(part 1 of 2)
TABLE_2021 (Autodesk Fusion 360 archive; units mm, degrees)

design "TABLE_2021" references "DistributeurCoin", "DistributeurBordure", "EchantillonRouge", "SupportCarreFouille", "BarreSeparation", "EchantillonVert", "CarreFouilleTresorJaune", "FriseJaune", "CarreFouille", "BaseTable", "CarreFouilleRadioactif", "Distributeur 2 Top", "Distributeur 2 Side", "CarreFouilleTresorViolet", "EchantillonBleu", "FriseViolet"
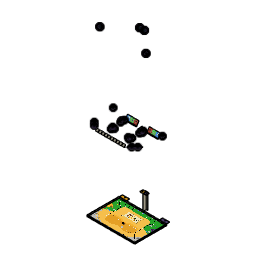
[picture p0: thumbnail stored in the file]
parameter "largeurCarreFouille" = 185 comment "largeur total du module de carre de fouille"
component_insert "Component Insert2" OffsetX 0 OffsetY 0 OffsetZ 0 AngleZ 0 OffsetX 0 OffsetY 0 OffsetZ 0 AngleZ 0 OffsetX 0 OffsetY 0 OffsetZ 0 AngleZ 0 OffsetX 0 OffsetY 0 OffsetZ 0 AngleZ 0 OffsetX 0 OffsetY 0 OffsetZ 0 AngleZ 0 OffsetX 0 OffsetY 0 OffsetZ 0 AngleZ 0 OffsetX 0 OffsetY 0 OffsetZ 0 AngleZ 0 OffsetX 0 OffsetY 0 OffsetZ 0 AngleZ 0 OffsetX 0 OffsetY 0 OffsetZ 0 AngleZ 0 OffsetX 0 OffsetY 0 OffsetZ 0 AngleZ 0 OffsetX 0 OffsetY 0 OffsetZ 0 AngleZ 0
joint "Assemble2" OffsetX 0 OffsetY 0 OffsetZ 0 AngleZ 0 alignAngle 180 alignOffsetX 0 alignOffsetY 0 alignOffsetZ 0
sketch "PlacementElements" plane through (0, 0, 0) normal (0, 0, 1) x axis (1, 0, 0)
  line L1 (3000, -2000) -> (0, -2000)
  line L2 (3000, 0) -> (3000, -2000)
  line L3 (0, 0) -> (3000, 0)
  line L4 (0, -2000) -> (0, 0)
  line L5 (1500, -2000) -> (1500, 0)
  line L6 (400, -400) -> (0, -400)
  line L7 (400, -1000) -> (400, -400)
  line L8 (0, -1000) -> (400, -1000)
  line L9 (0, -400) -> (0, -1000)
  line L10 (900, -555) -> (900, -795)
  line L11 (900, -675) -> (830, -675)
  line L12 (900, -720) -> (964.9519, -757.5)
  line L13 (835.0481, -757.5) -> (900, -720)
  line L14 (835.0481, -832.5) -> (835.0481, -757.5)
  line L15 (900, -870) -> (835.0481, -832.5)
  line L16 (964.9519, -832.5) -> (900, -870)
  line L17 (964.9519, -757.5) -> (964.9519, -832.5)
  line L18 (894.9519, -637.5) -> (894.9519, -712.5)
  line L19 (830, -600) -> (894.9519, -637.5)
  line L20 (765.0481, -637.5) -> (830, -600)
  line L21 (765.0481, -712.5) -> (765.0481, -637.5)
  line L22 (830, -750) -> (765.0481, -712.5)
  line L23 (894.9519, -712.5) -> (830, -750)
  line L24 (964.9519, -592.5) -> (900, -630)
  line L25 (964.9519, -517.5) -> (964.9519, -592.5)
  line L26 (900, -480) -> (964.9519, -517.5)
  line L27 (835.0481, -517.5) -> (900, -480)
  line L28 (835.0481, -592.5) -> (835.0481, -517.5)
  line L29 (900, -630) -> (835.0481, -592.5)
  line L30 (2100, -720) -> (2035.0481, -757.5)
  line L31 (2164.9519, -757.5) -> (2100, -720)
  line L32 (2164.9519, -832.5) -> (2164.9519, -757.5)
  line L33 (2100, -870) -> (2164.9519, -832.5)
  line L34 (2035.0481, -832.5) -> (2100, -870)
  line L35 (2035.0481, -757.5) -> (2035.0481, -832.5)
  line L36 (2170, -750) -> (2234.9519, -712.5)
  line L37 (2105.0481, -712.5) -> (2170, -750)
  line L38 (2105.0481, -637.5) -> (2105.0481, -712.5)
  line L39 (2170, -600) -> (2105.0481, -637.5)
  line L40 (2234.9519, -712.5) -> (2234.9519, -637.5)
  line L41 (2234.9519, -637.5) -> (2170, -600)
  line L42 (2035.0481, -592.5) -> (2100, -630)
  line L43 (2035.0481, -517.5) -> (2035.0481, -592.5)
  line L44 (2100, -480) -> (2035.0481, -517.5)
  line L45 (2164.9519, -517.5) -> (2100, -480)
  line L46 (2100, -630) -> (2164.9519, -592.5)
  line L47 (2164.9519, -592.5) -> (2164.9519, -517.5)
  line L48 (3000, -1000) -> (2600, -1000)
  line L49 (3000, -400) -> (3000, -1000)
  line L50 (2600, -1000) -> (2600, -400)
  line L51 (2600, -400) -> (3000, -400)
  line L52 (450, 22) -> (450, 222)
  line L53 (0, -2022) -> (1500, -2022)
  line L54 (800, -1550) -> (1150, -1550)
  line L55 (800, -1200) -> (800, -1550)
  line L56 (1150, -1200) -> (800, -1200)
  line L57 (1150, -1550) -> (1150, -1200)
  line L58 (800, -1200) -> (1150, -1550)
  line L59 (1150, -1200) -> (800, -1550)
  line L60 (975, -1200) -> (975, -1375)
  line L61 (800, -1375) -> (975, -1375)
  line L62 (2200, -1550) -> (1850, -1550)
  line L63 (1850, -1550) -> (1850, -1200)
  line L64 (1850, -1200) -> (2200, -1200)
  line L65 (2200, -1200) -> (2200, -1550)
  line L66 (-22, -2000) -> (-22, 0)
  line L67 (1450, -1300) -> (1550, -1300)
  line L68 (1450, -1200) -> (1450, -1300)
  line L69 (1550, -1200) -> (1450, -1200)
  line L70 (1550, -1300) -> (1550, -1200)
  line L71 (1450, -1200) -> (1550, -1300)
  line L72 (1550, -1200) -> (1450, -1300)
  point P6 (1500, 0)
  point P7 (1500, -2000)
  point P12 (1350, 0)
  point P13 (0, -1250)
  point P14 (0, -400)
  point P10 (900, -795)
  point P18 (900, -795)
  point P8 (900, -555)
  point P19 (900, -555)
  point P9 (830, -675)
  point P20 (830, -675)
  point P21 (900, -675)
  point P28 (900, -795)
  point P35 (830, -675)
  point P42 (900, -555)
  point P36 (900, -630)
  point P23 (900, -720)
  point P43 (3000, -1250)
  point P64 (3000, -400)
  point P15 (400, -400)
  point P65 (2600, -400)
  point P16 (400, -1000)
  point P62 (2600, -1000)
  point P17 (0, -1000)
  point P63 (3000, -1000)
  point P22 (964.9519, -757.5)
  point P44 (2035.0481, -757.5)
  point P45 (2100, -720)
  point P24 (835.0481, -757.5)
  point P46 (2164.9519, -757.5)
  point P25 (835.0481, -832.5)
  point P47 (2164.9519, -832.5)
  point P26 (900, -870)
  point P48 (2100, -870)
  point P27 (964.9519, -832.5)
  point P49 (2035.0481, -832.5)
  point P29 (894.9519, -712.5)
  point P52 (2105.0481, -712.5)
  point P30 (894.9519, -637.5)
  point P53 (2105.0481, -637.5)
  point P31 (830, -600)
  point P54 (2170, -600)
  point P32 (765.0481, -637.5)
  point P55 (2234.9519, -637.5)
  point P33 (765.0481, -712.5)
  point P50 (2234.9519, -712.5)
  point P34 (830, -750)
  point P51 (2170, -750)
  point P56 (2100, -630)
  point P37 (964.9519, -592.5)
  point P57 (2035.0481, -592.5)
  point P38 (964.9519, -517.5)
  point P58 (2035.0481, -517.5)
  point P39 (900, -480)
  point P59 (2100, -480)
  point P40 (835.0481, -517.5)
  point P60 (2164.9519, -517.5)
  point P41 (835.0481, -592.5)
  point P61 (2164.9519, -592.5)
  point P73 (2170, -675)
  point P74 (2100, -795)
  point P72 (2100, -555)
  point P75 (450, 0)
  point P77 (1650, 0)
  point P76 (2550, 0)
  point P80 (1500, -2022)
  point P81 (0, -2022)
  point P82 (1407.5, -2022)
  point P91 (1592.5, -2022)
  point P83 (1222.5, -2022)
  point P90 (1777.5, -2022)
  point P84 (1037.5, -2022)
  point P89 (1962.5, -2022)
  point P85 (852.5, -2022)
  point P88 (2147.5, -2022)
  point P86 (667.5, -2022)
  point P87 (2332.5, -2022)
  point P96 (975, -1375)
  point P11 (975, -1375)
  point P97 (975, -1375)
  point P98 (975, -1200)
  point P99 (975, -1375)
  point P100 (800, -1375)
  point P92 (1150, -1550)
  point P101 (1850, -1550)
  point P93 (800, -1550)
  point P102 (2200, -1550)
  point P94 (800, -1200)
  point P104 (2200, -1200)
  point P95 (1150, -1200)
  point P103 (1850, -1200)
  point P66 (892.3031, -1292.3031)
  point P107 (-22, -300)
  point P108 (-22, -337)
  point P109 (-22, -263)
  point P111 (3022, -300)
  point P112 (3022, -337)
  point P110 (3022, -263)
  point P117 (1500, -1250)
  point P1 (0, 0)
  point P113 (1550, -1300)
  point P116 (1550, -1200)
  point P114 (1450, -1300)
  midpoint L3 P6
  midpoint L1 P7
  coincident L3 P12
  coincident L4 P13
  horizontal L6
  vertical L7
  horizontal L8
  vertical L9
  coincident L4 P14
  coincident P10 P18
  coincident P8 P19
  vertical L10
  coincident P9 P20
  midpoint L10 P21
  horizontal L11
  coincident P10 P28
  coincident P9 P35
  coincident P8 P42
  coincident L10 P36
  vertical L18
  equal L19 L29
  equal L13 L23
  coincident L10 P23
  symmetric L5 P13 P43
  symmetric L5 P14 P64
  symmetric L5 P15 P65
  symmetric L5 P16 P62
  symmetric L5 P17 P63
  symmetric L5 P22 P44
  symmetric L5 P23 P45
  symmetric L5 P24 P46
  symmetric L5 P25 P47
  symmetric L5 P26 P48
  symmetric L5 P27 P49
  symmetric L5 P29 P52
  symmetric L5 P30 P53
  symmetric L5 P31 P54
  symmetric L5 P32 P55
  symmetric L5 P33 P50
  symmetric L5 P34 P51
  symmetric L5 P36 P56
  symmetric L5 P37 P57
  symmetric L5 P38 P58
  symmetric L5 P39 P59
  symmetric L5 P40 P60
  symmetric L5 P41 P61
  symmetric L5 P9 P73
  symmetric L5 P28 P74
  symmetric L5 P42 P72
  coincident L3 P75
  symmetric L5 P12 P77
  symmetric L5 P75 P76
  coincident P75 L52
  parallel L1 L53
  coincident L5 P80
  coincident L4 P81
  coincident L53 P82
  symmetric L5 P82 P91
  symmetric L5 P83 P90
  symmetric L5 P84 P89
  symmetric L5 P85 P88
  symmetric L5 P86 P87
  horizontal L54
  perpendicular L54 L55
  parallel L54 L56
  parallel L55 L57
  coincident L58 P96
  coincident L59 P96
  coincident P11 P97
  midpoint L56 P98
  coincident P11 P99
  midpoint L55 P100
  symmetric L5 P92 P101
  symmetric L5 P93 P102
  symmetric L5 P94 P104
  symmetric L5 P95 P103
  coincident P66 L58
  perpendicular L3 L66
  coincident L66 P107
  coincident L66 P108
  coincident L66 P109
  symmetric L5 P107 P111
  symmetric L5 P108 P112
  symmetric L5 P109 P110
  horizontal L67
  perpendicular L67 L68
  parallel L67 L69
  parallel L68 L70
  coincident L71 P117
  coincident L72 P117
  coincident L5 P117
  dimension "d26" distance L1 P11 = 625
  dimension "d27" distance L4 P11 = 975
  dimension "d28" distance L4 P10 = 900
  dimension "d29" distance P31 P34 = 150
  dimension "d31" distance L3 P35 = 675
  dimension "d32" distance P35 P42 = 120
  dimension "d33" distance P1 P13 = 1250
  dimension "d34" distance P14 P15 = 400
  dimension "d35" distance P15 P16 = 600
  dimension "d36" distance L3 L6 = 400
  dimension "d37" distance L10 P35 = 70
  dimension "d206" distance L5 P12 = 150
  dimension "d297" distance L1 P81 = 22
  dimension "d298" distance L5 P82 = 92.5 (= "largeurCarreFouille / 2")
  dimension "d425" distance L55 L57 = 350
  dimension "d426" distance L54 L56 = 350
  dimension "d427" distance P99 P100 = 175 (= "d426 / 2")
  dimension "d428" distance P97 P98 = 175 (= "d425 / 2")
  dimension "d549" distance L9 L66 = 22
  dimension "d550" distance P107 P109 = 37 (= "22 mm + 15 mm")
  dimension "d551" distance P107 P108 = 37 (= "d550")
  dimension "d552" distance P1 P107 = 300
  dimension "d605" distance P113 P116 = 100
  dimension "d606" distance P113 P114 = 100
  dimension "d607" distance L3 P117 = 1250
  dimension "d301" R-Pattern1-uDistance = 185 (= "largeurCarreFouille")
  dimension "d302" R-Pattern1-vDistance = 0
component_insert "Component Insert2"
component_insert "Insertion d'un composant22"
component_insert "Insertion d'un composant23"
component_insert "Component Insert4"
component_insert "Component Insert8"
component_insert "Insertion d'un composant24"
component_insert "Insertion d'un composant25"
component_insert "Component Insert11"
component_insert "Insertion d'un composant20"
component_insert "Insertion d'un composant21"
joint "Assemble3" OffsetX 0 OffsetY 0 OffsetZ 0 AngleZ 0 alignAngle 60 alignOffsetX 0 alignOffsetY 0 alignOffsetZ 0
joint "Assemble6" OffsetX 0 OffsetY 0 OffsetZ 0 AngleZ 0 alignAngle 15 alignOffsetX 0 alignOffsetY 0 alignOffsetZ 0
component_insert "Insertion d'un composant18"
component_insert "Insertion d'un composant19"
joint "Assemble9" OffsetX 0 OffsetY 0 OffsetZ 0 AngleZ 0 alignAngle -70 alignOffsetX 0 alignOffsetY 0 alignOffsetZ 0
joint "Assemble13" OffsetX 0 OffsetY 0 OffsetZ 0 AngleZ 0 alignAngle 60 alignOffsetX 0 alignOffsetY 0 alignOffsetZ 0 OffsetX 0 OffsetY 0 OffsetZ 0 AngleZ 0
component_insert "Insertion d'un composant3"
component_insert "Insertion d'un composant4"
joint "Assembler34" alignAngle -90 alignOffsetX 0 alignOffsetY 0 alignOffsetZ 0
joint "Assembler35" alignAngle -90 alignOffsetX 0 alignOffsetY 0 alignOffsetZ 0
component_insert "Component Insert3"
joint "Assemble19" OffsetX 0 OffsetY 0 OffsetZ 0 AngleZ 0 alignAngle -90 alignOffsetX 0 alignOffsetY 0 alignOffsetZ 0
component_insert "Component Insert5"
component_insert "Insertion d'un composant6"
component_insert "Insertion d'un composant7"
joint "Assemble20" OffsetX 0 OffsetY 0 OffsetZ 0 AngleZ 0 alignAngle 90 alignOffsetX 0 alignOffsetY 0 alignOffsetZ 0
joint "Assembler32" alignAngle 180 alignOffsetX 0 alignOffsetY 0 alignOffsetZ 0
joint "Assembler33" alignAngle 180 alignOffsetX 0 alignOffsetY 0 alignOffsetZ 0
component_insert "Component Insert3"
joint "Assemble21" OffsetX 0 OffsetY 0 OffsetZ 0 AngleZ 0 alignAngle 180 alignOffsetX 0 alignOffsetY 0 alignOffsetZ 0
component_insert "Insertion d'un composant11"
joint "Assembler36" alignAngle 180 alignOffsetX 0 alignOffsetY 0 alignOffsetZ 0
component_insert "Insertion d'un composant12"
joint "Assembler37" alignAngle 180 alignOffsetX 0 alignOffsetY 0 alignOffsetZ 0
component_insert "Insertion d'un composant13"
joint "Assembler38" alignAngle 180 alignOffsetX 0 alignOffsetY 0 alignOffsetZ 0
component_insert "Insertion d'un composant14"
joint "Assembler39" alignAngle 180 alignOffsetX 0 alignOffsetY 0 alignOffsetZ 0
component_insert "Insertion d'un composant15"
joint "Assembler40" alignAngle 180 alignOffsetX 0 alignOffsetY 0 alignOffsetZ 0
component_insert "Insertion d'un composant16"
joint "Assembler41" alignAngle 180 alignOffsetX 0 alignOffsetY 0 alignOffsetZ 0
component_insert "Insertion d'un composant17"
joint "Assembler42" alignAngle 180 alignOffsetX 0 alignOffsetY 0 alignOffsetZ 0
component_insert "Insertion d'un composant18"
joint "Assembler43" alignAngle 180 alignOffsetX 0 alignOffsetY 0 alignOffsetZ 0
component_insert "Insertion d'un composant19"
joint "Assembler44" alignAngle 180 alignOffsetX 0 alignOffsetY 0 alignOffsetZ 0
component_insert "Insertion d'un composant20"
joint "Assembler45" alignAngle 180 alignOffsetX 0 alignOffsetY 0 alignOffsetZ 0
component_insert "Insertion d'un composant8"
joint "Assembler46" alignAngle 90 alignOffsetX 0 alignOffsetY 0 alignOffsetZ 0
joint "Assembler47" alignAngle 0 alignOffsetX 0 alignOffsetY 0 alignOffsetZ 0
component_insert "Insertion d'un composant9"
joint "Assembler48" alignAngle 90 alignOffsetX 0 alignOffsetY 0 alignOffsetZ 0
joint "Assembler49" alignAngle 0 alignOffsetX 0 alignOffsetY 0 alignOffsetZ 0
component_insert "Insertion d'un composant14"
component_insert "Insertion d'un composant15"
component_insert "Insertion d'un composant16"
component_insert "Insertion d'un composant17"
component_insert "Component Insert1"
component_insert "Component Insert2"
component_insert "Component Insert3"
component_insert "Component Insert4"
component_insert "Component Insert5"
component_insert "Component Insert6"
component_insert "Component Insert7"
component_insert "Component Insert8"
component_insert "Component Insert9"
component_insert "Component Insert10"
joint "Assemble22" OffsetX 0 OffsetY 0 OffsetZ 0 AngleZ 0 alignAngle 180 alignOffsetX 0 alignOffsetY 0 alignOffsetZ 0
joint "Assemble23" OffsetX 0 OffsetY 0 OffsetZ 0 AngleZ 0 alignAngle 180 alignOffsetX 0 alignOffsetY 0 alignOffsetZ 0
joint "Assemble24" OffsetX 0 OffsetY 0 OffsetZ 0 AngleZ 0 alignAngle 180 alignOffsetX 0 alignOffsetY 0 alignOffsetZ 0
joint "Assemble25" OffsetX 0 OffsetY 0 OffsetZ 0 AngleZ 0 alignAngle 180 alignOffsetX 0 alignOffsetY 0 alignOffsetZ 0
joint "Assemble26" OffsetX 0 OffsetY 0 OffsetZ 0 AngleZ 0 alignAngle 180 alignOffsetX 0 alignOffsetY 0 alignOffsetZ 0
joint "Assemble27" OffsetX 0 OffsetY 0 OffsetZ 0 AngleZ 0 alignAngle 180 alignOffsetX 0 alignOffsetY 0 alignOffsetZ 0
joint "Assemble28" OffsetX 0 OffsetY 0 OffsetZ 0 AngleZ 0 alignAngle 180 alignOffsetX 0 alignOffsetY 0 alignOffsetZ 0
joint "Assemble29" OffsetX 0 OffsetY 0 OffsetZ 0 AngleZ 0 alignAngle 180 alignOffsetX 0 alignOffsetY 0 alignOffsetZ 0
joint "Assemble30" OffsetX 0 OffsetY 0 OffsetZ 0 AngleZ 0 alignAngle 180 alignOffsetX 0 alignOffsetY 0 alignOffsetZ 0
joint "Assemble31" OffsetX 0 OffsetY 0 OffsetZ 0 AngleZ 0 alignAngle 180 alignOffsetX 0 alignOffsetY 0 alignOffsetZ 0
joint "Assembler54" alignAngle -15 alignOffsetX 0 alignOffsetY 0 alignOffsetZ 0
joint "Assembler55" alignAngle 15 alignOffsetX 0 alignOffsetY 0 alignOffsetZ 0
joint "Assembler56" alignAngle 75 alignOffsetX 0 alignOffsetY 0 alignOffsetZ 0
joint "Assembler57" alignAngle 25 alignOffsetX 0 alignOffsetY 0 alignOffsetZ 0
joint "Assembler58" alignAngle 60 alignOffsetX 0 alignOffsetY 0 alignOffsetZ 0
joint "Assembler59" alignAngle 60 alignOffsetX 0 alignOffsetY 0 alignOffsetZ 0
joint "Assembler60" alignAngle 60 alignOffsetX 0 alignOffsetY 0 alignOffsetZ 0
joint "Assembler61" alignAngle 60 alignOffsetX 0 alignOffsetY 0 alignOffsetZ 0
component_insert "Insertion d'un composant10"
joint "Assembler62" alignAngle -90 alignOffsetX 0 alignOffsetY 0 alignOffsetZ 48 (= "70.00 mm - 22 mm")
component_insert "Insertion d'un composant11"
joint "Assembler63" alignAngle 180 alignOffsetX 0 alignOffsetY 0 alignOffsetZ 0
component_insert "Insertion d'un composant26"
component_insert "Insertion d'un composant27"
joint "Assembler67" alignAngle 90 alignOffsetX 0 alignOffsetY 0 alignOffsetZ 48
component_insert "Insertion d'un composant5"
joint "Assembler68" alignAngle -270 alignOffsetX 0 alignOffsetY -55 alignOffsetZ 0
joint "Assembler69" alignAngle -75 alignOffsetX 0 alignOffsetY 0 alignOffsetZ 0
joint "Assembler70" alignAngle 105 alignOffsetX 0 alignOffsetY 0 alignOffsetZ 0
joint "Assembler71" alignAngle -75 alignOffsetX 0 alignOffsetY 0 alignOffsetZ 0
joint "Assembler72" alignAngle 105 alignOffsetX 0 alignOffsetY 0 alignOffsetZ 0
joint "Assembler73" alignAngle 180 alignOffsetX 0 alignOffsetY 22 alignOffsetZ 0
joint "Assembler74" alignAngle 180 alignOffsetX 0 alignOffsetY 22 alignOffsetZ 0
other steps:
joint_origin "JointOrigin2" OffsetX 0 OffsetY 0 OffsetZ 0 AngleZ 0
create_component "CreateComponent1"
create_component "CreateComponent2"
create_component "CreateComponent3"
joint_origin "JointOrigin22" OffsetX 0 OffsetY 0 OffsetZ 0 AngleZ 0
joint_origin "JointOrigin23" OffsetX 0 OffsetY 0 OffsetZ 0 AngleZ 0
joint_origin "JointOrigin24" sketch "PlacementElements" OffsetX 0 OffsetY 0 OffsetZ 0 AngleZ 0
create_component "CreateComponent4"
joint_origin "JointOrigin25" OffsetX 0 OffsetY 0 OffsetZ 0 AngleZ 0
joint_origin "JointOrigin26" OffsetX 0 OffsetY 0 OffsetZ 0 AngleZ 0
joint_origin "JointOrigin27" OffsetX 0 OffsetY 0 OffsetZ 0 AngleZ 0
joint_origin "JointOrigin28" OffsetX 0 OffsetY 0 OffsetZ 0 AngleZ 0
joint_origin "JointOrigin29" OffsetX 0 OffsetY 0 OffsetZ 0 AngleZ 0
joint_origin "JointOrigin30" OffsetX 0 OffsetY 0 OffsetZ 0 AngleZ 0
joint_origin "JointOrigin31" OffsetX 0 OffsetY 0 OffsetZ 0 AngleZ 0
joint_origin "JointOrigin32" OffsetX 0 OffsetY 0 OffsetZ 0 AngleZ 0
joint_origin "JointOrigin33" OffsetX 0 OffsetY 0 OffsetZ 0 AngleZ 0
joint_origin "JointOrigin34" OffsetX 0 OffsetY 0 OffsetZ 0 AngleZ 0
joint_origin "JointOrigin35"
joint_origin "JointOrigin36"
joint_origin "JointOrigin51"
joint_origin "JointOrigin52"
joint_origin "JointOrigin53"
joint_origin "JointOrigin56"
joint_origin "JointOrigin57"
joint_origin "JointOrigin62"
joint_origin "JointOrigin63"
joint_origin "JointOrigin64"
joint_origin "JointOrigin65"
joint_origin "JointOrigin66"
joint_origin "JointOrigin67"
joint_origin "JointOrigin69"
joint_origin "JointOrigin79"
joint_origin "JointOrigin81"
joint_origin "JointOrigin82"
joint_origin "JointOrigin83"
joint_origin "JointOrigin84"
joint_origin "JointOrigin85"
joint_origin "JointOrigin86"
joint_origin "JointOrigin87"
joint_origin "JointOrigin88"
joint_origin "JointOrigin90"
joint_origin "JointOrigin91"
joint_origin "JointOrigin92"
joint_origin "JointOrigin93"
joint_origin "JointOrigin94"
joint_origin "JointOrigin95"

design "DistributeurBordure" references "EchantillonBleu"
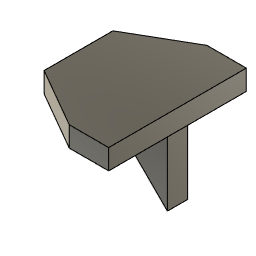
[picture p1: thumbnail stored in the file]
parameter "d10" = 70
sketch "Esquisse1" plane through (0, 0, 0) normal (0, 0, 1) x axis (1, 0, 0)
  line L1 (0, -100) -> (0, 100)
  line L2 (-22, -100) -> (0, -100)
  line L3 (-22, 100) -> (-22, -100)
  line L4 (0, 100) -> (-22, 100)
  point P1 (0, 0)
  vertical L1
  perpendicular L1 L2
  perpendicular L2 L3
  perpendicular L1 L4
  dimension "d1" distance L1 L3 = 22
  dimension "d2" distance P1 L4 = 100
  dimension "d3" distance L2 L4 = 200 (= "d2 * 2")
extrude "Extrusion1" new body sketch "Esquisse1" along normal blind 92 (= "70 mm + 22 mm")
sketch "Esquisse1" plane through (0, 0, 92) normal (0, 0, 1) x axis (-1, 0, 0)
  line L1 (22, 100) -> (22, -100)
  line L2 (0, 100) -> (22, 100)
  line L3 (0, -100) -> (0, 100)
  line L4 (22, -100) -> (0, -100)
  line L5 (0, -37) -> (64.287, -37)
  line L6 (0, -15) -> (0, -37)
  line L7 (64.287, -15) -> (0, -15)
  line L8 (64.287, -37) -> (64.287, -15)
  line L9 (64.287, 15) -> (0, 15)
  line L10 (64.287, 37) -> (64.287, 15)
  line L11 (0, 37) -> (64.287, 37)
  line L12 (0, 15) -> (0, 37)
  point P8 (0, -15)
  point P10 (0, 15)
  point P1 (0, 0)
  point P11 (64.287, 15)
  point P12 (64.287, 37)
  point P6 (64.287, -37)
  point P9 (64.287, -15)
  horizontal L5
  vertical L6
  horizontal L7
  vertical L8
  coincident L3 P8
  horizontal L9
  vertical L10
  horizontal L11
  vertical L12
  coincident L3 P10
  dimension "d6" distance P1 P8 = 15
  dimension "d7" distance P1 P10 = 15 (= "d6")
  dimension "d8" distance P11 P12 = 22
  dimension "d9" distance P6 P9 = 22 (= "d8")
  dimension "d42" distance L1 L8 = 42.287
  dimension "d43" distance L1 L10 = 42.287 (= "d42")
extrude "Extrusion1" new body sketch "Esquisse1" profile of L1 L5 L7 L8 L9 L10 L11 against normal blind 92
extrude "Extrusion2" add sketch "Esquisse1" profile of L1 L3 L5 L6 L7 L8 L9 L10 L11 L12 along normal blind 120
sketch "Esquisse2" plane through (0, -37, 0) normal (0, -1, 0) x axis (1, 0, 0)
  line L1 (-64.287, 0) -> (-64.287, 212)
  line L2 (-22, 0) -> (-64.287, 0)
  line L3 (-22, 92) -> (-22, 0)
  line L4 (0, 92) -> (-22, 92)
  line L5 (0, 212) -> (0, 92)
  line L6 (-64.287, 212) -> (0, 212)
  line L7 (-64.287, 175.3484) -> (-4.8706, 72.4361)
  line L8 (0, 108) -> (-19.0526, 97)
  line L9 (-11, 127.0526) -> (0, 108)
  line L10 (-30.0526, 116.0526) -> (-11, 127.0526)
  line L11 (-27.7128, 92) -> (-64.287, 155.3484)
  line L12 (-19.0526, 97) -> (-27.7128, 92)
  line L13 (-64.287, 92) -> (-22, 92)
  line L14 (-22, 82.1051) -> (-27.7128, 92)
  point P9 (-64.287, 175.3484)
  point P10 (-19.0526, 97)
  point P13 (-30.0526, 116.0526)
  point P14 (-64.287, 155.3484)
  point P16 (-19.0526, 97)
  point P11 (0, 108)
  point P5 (-22, 92)
  point P17 (-22, 92)
  point P18 (-64.287, 92)
  point P15 (-27.7128, 92)
  point P19 (-22, 82.1051)
  point P12 (-11, 127.0526)
  coincident L1 P9
  coincident L7 P10
  perpendicular L7 L8
  perpendicular L8 L9
  coincident L7 P13
  perpendicular L7 L10
  coincident L1 P14
  parallel L7 L11
  coincident L7 P16
  perpendicular L7 L12
  collinear L8 L12
  coincident L5 P11
  coincident P5 P17
  coincident L1 P18
  perpendicular L1 L13
  coincident P15 L13
  coincident L3 P19
  perpendicular L12 L14
  dimension "d16" distance P11 P12 = 22
  dimension "d17" distance P10 P11 = 22
  dimension "d18" angle L5 L7 = 30
  dimension "d19" distance L7 L11 = 10
extrude "Extrusion3" cut sketch "Esquisse2" profile of L1 L4 L5 L6 L7 L8 L9 L10 L11 L12 L13 against normal blind 74
sketch "Esquisse1" plane through (19.0526, 0, 11) normal (0.866, 0, 0.5) x axis (0, 1, 0)
  line L1 (-15, 166.6791) -> (-15, 93.5307)
  line L2 (-37, 93.5307) -> (-37, 166.6791)
  line L3 (-15, 93.5307) -> (-37, 93.5307)
  line L4 (15, 93.5307) -> (15, 166.6791)
  line L5 (37, 93.5307) -> (15, 93.5307)
  line L6 (37, 166.6791) -> (37, 93.5307)
  line L7 (37.5, 93.5307) -> (-37.5, 93.5307)
  line L8 (37.5, 223.5307) -> (37.5, 93.5307)
  line L9 (-37.5, 223.5307) -> (37.5, 223.5307)
  line L10 (-37.5, 93.5307) -> (-37.5, 223.5307)
  line L11 (37.5, 166.6791) -> (37, 166.6791)
  line L12 (-37.5, 166.6791) -> (-37, 166.6791)
  line L13 (-37, 166.6791) -> (-15, 166.6791)
  line L14 (15, 166.6791) -> (37, 166.6791)
  point P9 (37, 166.6791)
  point P14 (37, 166.6791)
  point P15 (37.5, 166.6791)
  point P4 (-37, 166.6791)
  point P16 (-37, 166.6791)
  point P17 (-37.5, 166.6791)
  point P12 (37.5, 223.5307)
  point P13 (-37.5, 223.5307)
  perpendicular L2 L7
  perpendicular L3 L8
  perpendicular L8 L9
  perpendicular L9 L10
  collinear L5 L7
  coincident P9 P14
  coincident L8 P15
  perpendicular L8 L11
  coincident P4 P16
  coincident L10 P17
  perpendicular L10 L12
  equal L11 L12
  dimension "d22" distance P12 P13 = 75
  dimension "d23" distance L7 L9 = 130
extrude "Extrusion1" new body sketch "Esquisse1" profile of L1 L2 L3 L4 L5 L6 L7 L8 L9 L10 along normal blind 10
sketch "Esquisse1" plane through (0, -37.5, 0) normal (0, -1, 0) x axis (1, 0, 0)
  line L1 (-27.7128, 92) -> (-92.7128, 204.5833)
  line L2 (-19.0526, 97) -> (-27.7128, 92)
  line L3 (-84.0526, 209.5833) -> (-19.0526, 97)
  line L4 (-92.7128, 204.5833) -> (-84.0526, 209.5833)
  line L5 (0, 108) -> (-19.0526, 97)
  line L6 (-11, 127.0526) -> (0, 108)
  line L7 (-30.0526, 116.0526) -> (-11, 127.0526)
  line L8 (-30.0526, 116.0526) -> (-19.0526, 97)
  point P4 (-19.0526, 97)
  point P6 (-19.0526, 97)
  point P9 (-30.0526, 116.0526)
  point P10 (-19.0526, 97)
  point P7 (0, 108)
  point P8 (-11, 127.0526)
  coincident P4 P6
  perpendicular L3 L5
  perpendicular L5 L6
  coincident L3 P9
  perpendicular L3 L7
  coincident P4 P10
  dimension "d26" distance P7 P8 = 22
  dimension "d27" distance P8 P9 = 22
extrude "Extrusion1" new body sketch "Esquisse1" profile of L3 L5 L6 L7 L8 against normal blind 75
joint "Assembler1" alignAngle 180 alignOffsetX 0 alignOffsetY 0 alignOffsetZ 0
joint "Assembler2" alignAngle -90 alignOffsetX 0 alignOffsetY 0 alignOffsetZ 15
joint "Assembler3" alignAngle 0 alignOffsetX 0 alignOffsetY 0 alignOffsetZ 0
sketch "Esquisse1" plane through (0, -37, 0) normal (0, -1, 0) x axis (1, 0, 0)
  line L1 (-64.287, 155.3484) -> (-27.7128, 92)
  line L2 (-64.287, 0) -> (-64.287, 155.3484)
  line L3 (-22, 0) -> (-64.287, 0)
  line L4 (-22, 92) -> (-22, 0)
  line L5 (-27.7128, 92) -> (-22, 92)
  line L6 (-22, 82.1051) -> (-27.7128, 92)
  point P2 (-27.7128, 92)
  point P7 (-27.7128, 92)
  coincident P2 P7
  parallel L1 L6
extrude "Extrusion4" cut sketch "Esquisse1" profile of L4 L5 L6 against normal blind 74
sketch "Esquisse1" plane through (0, 0, 92) normal (0, 0, 1) x axis (-1, 0, 0)
  line L1 (22, 100) -> (22, -100)
  line L2 (0, 100) -> (22, 100)
  line L3 (0, -100) -> (0, 100)
  line L4 (22, -100) -> (0, -100)
  line L5 (132, -75) -> (22, -75)
  line L6 (132, 75) -> (132, -75)
  line L7 (22, 75) -> (132, 75)
  point P6 (22, -75)
  point P9 (22, 75)
  point P1 (0, 0)
  coincident L1 P6
  perpendicular L1 L5
  perpendicular L5 L6
  coincident L1 P9
  perpendicular L1 L7
  dimension "d46" distance P1 L5 = 75 (= "( 150 / 2 ) * 1 mm")
  dimension "d47" distance P1 L7 = 75 (= "d46")
  dimension "d48" distance L1 L6 = 110
extrude "Extrusion1" new body sketch "Esquisse1" profile of L1 L5 L6 L7 against normal blind 22
joint "Assembler4" alignAngle 0 alignOffsetX 0 alignOffsetY 0 alignOffsetZ 0
sketch "Esquisse1" plane through (0, 0, 0) normal (0, 1, 0) x axis (1, 0, 0)
  line L1 (-132, -70) -> (-22, -70)
  line L2 (-22, 0) -> (-22, -70)
  line L3 (-92, -70) -> (-22, 0)
  point P2 (-22, -70)
  point P4 (-22, -70)
  point P6 (-92, -70)
  point P5 (-22, 0)
  coincident P2 P4
  perpendicular L1 L2
  coincident L1 P6
  dimension "d55" distance P4 P5 = 70 (= "92 mm - 22 mm")
  dimension "d56" distance P4 P6 = 70 (= "d55")
extrude "Extrusion1" new body sketch "Esquisse1" distance 11
as_built_joint "Réelle"
sketch "Esquisse2" plane through (0, 0, 92) normal (0, 0, 1) x axis (-1, 0, 0)
  line L1 (132, -75) -> (22, -75)
  line L2 (132, 75) -> (132, -75)
  line L3 (22, 75) -> (132, 75)
  line L4 (22, -75) -> (22, 75)
  line L5 (64.9519, -75) -> (0, -37.5)
  line L6 (129.9038, -37.5) -> (64.9519, -75)
  line L7 (129.9038, 37.5) -> (129.9038, -37.5)
  line L8 (64.9519, 75) -> (129.9038, 37.5)
  line L9 (0, 37.5) -> (64.9519, 75)
  line L10 (0, -37.5) -> (0, 37.5)
  point P1 (0, 0)
  point P8 (129.9038, -37.5)
  point P12 (64.9519, 0)
  midpoint P1 L10
  dimension "d59" distance P8 P12 = 75 (= "( 150 / 2 ) * 1 mm")
  dimension "d60" distance L4 L10 = 22
extrude "Extrusion2" cut sketch "Esquisse2" profile of L1 L2 L3 L6 L7 L8 against normal blind 22
component_insert "Insertion d'un composant"
joint "Assembler5" alignAngle 0 alignOffsetX 0 alignOffsetY 0 alignOffsetZ 0
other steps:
create_component "CreateComponent1"
create_component "CreateComponent2"
create_component "CreateComponent3"
create_component "CreateComponent4"
joint_origin "JointOrigin1"
joint_origin "JointOrigin1"
joint_origin "JointOrigin2"
joint_origin "JointOrigin1"
joint_origin "JointOrigin3"
joint_origin "JointOrigin2"
create_component "CreateComponent5"
joint_origin "JointOrigin1"
joint_origin "JointOrigin1"
create_component "CreateComponent6"
joint_origin "JointOrigin2"

design "EchantillonBleu"
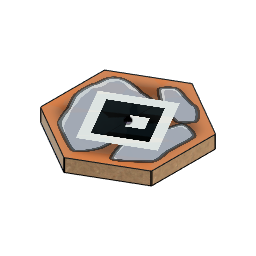
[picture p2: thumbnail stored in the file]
parameter "diaEchantillon" = 150
parameter "epEchantillon" = 15
sketch "Sketch1" plane through (0, 0, 0) normal (0, 0, 1) x axis (1, 0, 0)
  line L1 (0, 75) -> (64.9519, 37.5)
  line L2 (-64.9519, 37.5) -> (0, 75)
  line L3 (-64.9519, -37.5) -> (-64.9519, 37.5)
  line L4 (0, -75) -> (-64.9519, -37.5)
  line L5 (64.9519, -37.5) -> (0, -75)
  line L6 (64.9519, 37.5) -> (64.9519, -37.5)
  point P1 (0, 0)
  point P8 (0, 0)
  point P3 (0, 75)
  coincident P1 P8
  vertical L6
  dimension "d3" distance P3 P8 = 75 (= "diaEchantillon / 2")
extrude "Extrude1" new body sketch "Sketch1" along normal blind 15 (= "epEchantillon")
fillet "Congé" radius 1
decal "Décalcomanie1"
decal "Décalcomanie2"
sketch "Esquisse" plane through (0, 0, 15) normal (0, 0, 1) x axis (-1, 0, 0)
  line L1 (64.9519, 36.9226) -> (64.9519, -36.9226)
  line L2 (0.5, 74.7113) -> (64.4519, 37.7887)
  line L3 (-64.4519, 37.7887) -> (-0.5, 74.7113)
  line L4 (-64.9519, -36.9226) -> (-64.9519, 36.9226)
  line L5 (-0.5, -74.7113) -> (-64.4519, -37.7887)
  line L6 (64.4519, -37.7887) -> (0.5, -74.7113)
  arc A1 centre (63.9519, -36.9226) radius 1 clockwise from (64.9519, -36.9226) to (64.4519, -37.7887)
  arc A2 centre (63.9519, 36.9226) radius 1 clockwise from (64.4519, 37.7887) to (64.9519, 36.9226)
  arc A3 centre (0, 73.8453) radius 1 clockwise from (-0.5, 74.7113) to (0.5, 74.7113)
  arc A4 centre (-63.9519, 36.9226) radius 1 clockwise from (-64.9519, 36.9226) to (-64.4519, 37.7887)
  arc A5 centre (-63.9519, -36.9226) radius 1 clockwise from (-64.4519, -37.7887) to (-64.9519, -36.9226)
  arc A6 centre (0, -73.8453) radius 1 clockwise from (0.5, -74.7113) to (-0.5, -74.7113)
  point P1 (0, 0)
  point P20 (0, 0)
  coincident P1 P20

design "MiddleBeaconTop"
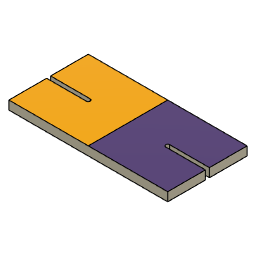
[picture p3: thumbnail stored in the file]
work_plane "WorkPlane1" AlongDistance 1000
sketch "Sketch1" plane through (0, 1000, 0) normal (0, 1, 0) x axis (1, 0, 0)
  line L1 (200, -100) -> (-200, -100)
  line L2 (200, 100) -> (200, -100)
  line L3 (-200, 100) -> (200, 100)
  line L4 (-200, -100) -> (-200, 100)
  line L5 (200, 100) -> (-200, -100)
  line L6 (-200, 100) -> (200, -100)
  line L7 (-100, -5) -> (-200, -5)
  line L8 (-200, 5) -> (-100, 5)
  line L9 (-100, 0) -> (-200, 0)
  line L10 (100, 5) -> (200, 5)
  line L11 (200, -5) -> (100, -5)
  line L12 (100, 0) -> (200, 0)
  arc A1 centre (-100, 0) radius 5 clockwise from (-100, 5) to (-100, -5)
  arc A2 centre (-200, 0) radius 5 clockwise from (-200, -5) to (-200, 5)
  arc A3 centre (100, 0) radius 5 clockwise from (100, -5) to (100, 5)
  arc A4 centre (200, 0) radius 5 clockwise from (200, 5) to (200, -5)
  point P6 (0, 0)
  point P1 (0, 0)
  point P11 (-200, 0)
  point P17 (200, 0)
  point P4 (200, 100)
  point P5 (-200, 100)
  point P3 (200, -100)
  point P12 (-100, 0)
  perpendicular L1 L2
  parallel L1 L3
  parallel L2 L4
  horizontal L1
  coincident L5 P6
  coincident L6 P6
  coincident P1 P6
  tangent L7 A1
  tangent A1 L8
  parallel L7 L8
  tangent L8 A2
  tangent L7 A2
  perpendicular L4 L9
  midpoint L4 P11
  tangent L10 A3
  tangent A3 L11
  parallel L10 L11
  tangent L11 A4
  tangent L10 A4
  perpendicular L2 L12
  midpoint L2 P17
  equal A1 A3
  equal L9 L12
  dimension "d2" distance P4 P5 = 400
  dimension "d3" distance P3 P4 = 200
  dimension "d4" distance P11 P12 = 100
  dimension "d5" radius A1 = 5
extrude "Extrude1" new body sketch "Sketch1" profile of L1 L2 L3 L4 L7 A1 L8 L10 A3 L11 against normal blind 22
work_plane "WorkPlane2"
split_face "SplitFace1"

design "EchantillonRouge"
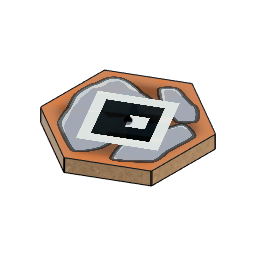
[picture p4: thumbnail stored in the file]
parameter "diaEchantillon" = 150
parameter "epEchantillon" = 15
sketch "Sketch1" plane through (0, 0, 0) normal (0, 0, 1) x axis (1, 0, 0)
  line L1 (0, 75) -> (64.9519, 37.5)
  line L2 (-64.9519, 37.5) -> (0, 75)
  line L3 (-64.9519, -37.5) -> (-64.9519, 37.5)
  line L4 (0, -75) -> (-64.9519, -37.5)
  line L5 (64.9519, -37.5) -> (0, -75)
  line L6 (64.9519, 37.5) -> (64.9519, -37.5)
  point P1 (0, 0)
  point P8 (0, 0)
  point P3 (0, 75)
  coincident P1 P8
  vertical L6
  dimension "d3" distance P3 P8 = 75 (= "diaEchantillon / 2")
extrude "Extrude1" new body sketch "Sketch1" along normal blind 15 (= "epEchantillon")
fillet "Congé" radius 1
decal "Décalcomanie1"
decal "Décalcomanie2"
sketch "Esquisse" plane through (0, 0, 15) normal (0, 0, 1) x axis (-1, 0, 0)
  line L1 (64.9519, 36.9226) -> (64.9519, -36.9226)
  line L2 (0.5, 74.7113) -> (64.4519, 37.7887)
  line L3 (-64.4519, 37.7887) -> (-0.5, 74.7113)
  line L4 (-64.9519, -36.9226) -> (-64.9519, 36.9226)
  line L5 (-0.5, -74.7113) -> (-64.4519, -37.7887)
  line L6 (64.4519, -37.7887) -> (0.5, -74.7113)
  arc A1 centre (63.9519, -36.9226) radius 1 clockwise from (64.9519, -36.9226) to (64.4519, -37.7887)
  arc A2 centre (63.9519, 36.9226) radius 1 clockwise from (64.4519, 37.7887) to (64.9519, 36.9226)
  arc A3 centre (0, 73.8453) radius 1 clockwise from (-0.5, 74.7113) to (0.5, 74.7113)
  arc A4 centre (-63.9519, 36.9226) radius 1 clockwise from (-64.9519, 36.9226) to (-64.4519, 37.7887)
  arc A5 centre (-63.9519, -36.9226) radius 1 clockwise from (-64.4519, -37.7887) to (-64.9519, -36.9226)
  arc A6 centre (0, -73.8453) radius 1 clockwise from (0.5, -74.7113) to (-0.5, -74.7113)
  point P1 (0, 0)
  point P20 (0, 0)
  coincident P1 P20

design "BarreSeparation"
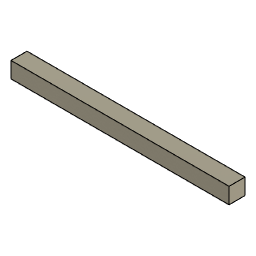
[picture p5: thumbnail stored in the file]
sketch "Sketch1" plane through (0, 0, 0) normal (1, 0, 0) x axis (0, 1, 0)
  line L1 (-11, 0) -> (11, 0)
  line L2 (-11, 22) -> (-11, 0)
  line L3 (11, 22) -> (-11, 22)
  line L4 (11, 0) -> (11, 22)
  line L5 (-11, 22) -> (11, 0)
  line L6 (11, 22) -> (-11, 0)
  point P6 (0, 11)
  point P1 (0, 0)
  point P4 (-11, 22)
  point P5 (11, 22)
  horizontal L1
  perpendicular L1 L2
  parallel L1 L3
  parallel L2 L4
  coincident L5 P6
  coincident L6 P6
  midpoint P1 L1
  equal L3 L4
  dimension "d1" distance P4 P5 = 22
extrude "Extrude1" new body sketch "Sketch1" profile of L1 L2 L3 L4 along normal blind 300

design "Frise"
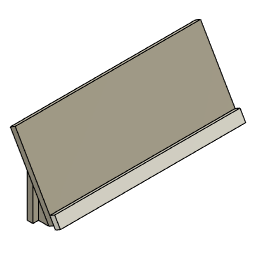
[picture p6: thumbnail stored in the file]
parameter "hauteurFrise" = 300
parameter "largeurFrise" = 720
parameter "angleFrise" = 30
parameter "epaisseurFrise" = 22
sketch "Sketch1" plane through (0, 0, 0) normal (1, 0, 0) x axis (0, 1, 0)
  line L1 (600, 70) -> (-600, 70)
  line L2 (600, 0) -> (600, 70)
  line L3 (-600, 0) -> (600, 0)
  line L4 (-600, 70) -> (-600, 0)
  point P1 (0, 0)
  point P3 (600, 70)
  point P4 (600, 0)
  point P2 (-600, 70)
  horizontal L1
  vertical L2
  horizontal L3
  vertical L4
  midpoint P1 L3
  dimension "d1" distance P3 P4 = 70
  dimension "d2" distance P2 P3 = 1200
extrude "Extrude1" new body sketch "Sketch1" against normal blind 22
sketch "Sketch2" plane through (0, 0, 0) normal (0, 0, -1) x axis (1, 0, 0)
  line L1 (0, 600) -> (0, -600)
  line L2 (-22, 600) -> (0, 600)
  line L3 (-22, -600) -> (-22, 600)
  line L4 (0, -600) -> (-22, -600)
  line L5 (978, 600) -> (-22, 600)
  line L6 (978, -600) -> (978, 600)
  line L7 (-22, -600) -> (978, -600)
  line L8 (-22, 600) -> (-22, -600)
  point P4 (-22, 600)
  point P6 (-22, 600)
  point P2 (0, -600)
  point P7 (978, 600)
  horizontal L5
  vertical L6
  horizontal L7
  vertical L8
  coincident P4 P6
  coincident P2 L7
  dimension "d5" distance P6 P7 = 1000
extrude "Extrude2" add sketch "Sketch2" along normal blind 22
sketch "Sketch3" plane through (0, 0, 0) normal (0, 1, 0) x axis (1, 0, 0)
  line L1 (0, -70) -> (0, 0)
  line L2 (40.4145, 0) -> (0, -70)
  line L3 (0, 0) -> (40.4145, 0)
  line L4 (0, -75.899) -> (0, -70)
  line L5 (0, -118.8533) -> (0, -75.899)
  line L6 (59.4671, -11) -> (40.4145, 0)
  line L7 (-90.5329, -270.8076) -> (59.4671, -11)
  line L8 (-109.5855, -259.8076) -> (-90.5329, -270.8076)
  line L9 (40.4145, 0) -> (-109.5855, -259.8076)
  line L10 (78.5196, -22) -> (59.4671, -11)
  line L11 (62.8696, -49.1066) -> (78.5196, -22)
  line L12 (43.8171, -38.1066) -> (62.8696, -49.1066)
  line L13 (59.4671, -11) -> (43.8171, -38.1066)
  point P1 (0, 0)
  point P2 (0, 0)
  point P5 (0, 0)
  point P3 (0, -70)
  point P4 (40.4145, 0)
  point P8 (59.4671, -11)
  point P9 (-90.5329, -270.8076)
  point P12 (62.8696, -49.1066)
  point P13 (43.8171, -38.1066)
  point P11 (78.5196, -22)
  coincident P1 P2
  vertical L1
  coincident P1 P5
  perpendicular L1 L3
  parallel L1 L5
  perpendicular L6 L7
  parallel L6 L8
  parallel L7 L9
  perpendicular L2 L6
  perpendicular L10 L11
  parallel L10 L12
  parallel L11 L13
  perpendicular L7 L10
  dimension "d10" distance P2 P3 = 70
  dimension "d13" angle L2 L5 = 30 (= "angleFrise")
  dimension "d14" distance P4 P8 = 22 (= "epaisseurFrise")
  dimension "d15" distance P8 P9 = 300 (= "hauteurFrise")
  dimension "d18" distance P12 P13 = 22 (= "epaisseurFrise")
  dimension "d19" distance P11 P12 = 31.3
extrude "Extrude1" new body sketch "Sketch3" profile of L2 L6 L7 L8 L9 distance 360 (= "largeurFrise / 2")
ground "Ground1"
extrude "Extrude1" new body sketch "Sketch3" profile of L7 L10 L11 L12 L13 distance 720 (= "largeurFrise")
extrude "Extrude1" sketch "Sketch3" profile of L1 L2 L3 L9 blind 22 (= "epaisseurFrise")
extrude "Extrude1" sketch "Sketch3" profile of L1 L2 L3 L9 no distance stored
extrude "Extrude1" new body sketch "Sketch3" profile of L1 L2 L3 L9 distance 22 (= "epaisseurFrise")
joint "Assemble1" alignAngle 0 alignOffsetX 0 alignOffsetY 0 alignOffsetZ 0
joint "Assemble2" alignAngle -90 alignOffsetX 0 alignOffsetY 0 alignOffsetZ 0
joint "Assemble3" alignAngle 210 (= "180 deg + angleFrise") alignOffsetX 0 alignOffsetY 0 alignOffsetZ 0
joint "Assemble4" alignAngle -90 alignOffsetX 0 alignOffsetY 0 alignOffsetZ 0
joint "Assemble5" alignAngle 0 alignOffsetX 0 alignOffsetY 0 alignOffsetZ 0
ground "Ground2"
as_built_joint "As-built1"
sketch "Esquisse1" plane through (0, -360, 0) normal (0, -1, 0) x axis (1, 0, 0)
  line L1 (43.8171, 38.1066) -> (62.8696, 49.1066)
  line L2 (59.4671, 11) -> (43.8171, 38.1066)
  line L3 (78.5196, 22) -> (59.4671, 11)
  line L4 (62.8696, 49.1066) -> (78.5196, 22)
  line L5 (65.8179, 0) -> (59.4671, 11)
  line L6 (84.8705, 11) -> (65.8179, 0)
  line L7 (78.5196, 22) -> (84.8705, 11)
  line L8 (0, 0) -> (40.4145, 0)
  point P4 (59.4671, 11)
  point P6 (59.4671, 11)
  point P5 (78.5196, 22)
  point P9 (78.5196, 22)
  point P7 (65.8179, 0)
  coincident P4 P6
  perpendicular L3 L5
  perpendicular L2 L6
  coincident P5 P9
  perpendicular L6 L7
  coincident P7 L8
extrude "Extrusion2" add sketch "Esquisse1" profile of L3 L5 L6 L7 against normal blind 720
sketch "Esquisse1" plane through (0, -360, 0) normal (0, -1, 0) x axis (1, 0, 0)
  line L1 (0, 70) -> (40.4145, 0)
  line L2 (0, 0) -> (0, 70)
  line L3 (40.4145, 0) -> (0, 0)
  line L4 (-22, 108.1051) -> (-22, 0)
  line L5 (-44, 146.2102) -> (-22, 108.1051)
  line L6 (-44, 0) -> (-44, 146.2102)
  line L7 (-22, 0) -> (-44, 0)
  line L8 (40.4145, 0) -> (-109.5855, 259.8076)
  point P6 (-22, 108.1051)
  point P7 (-44, 146.2102)
  point P5 (-22, 0)
  point P8 (-44, 0)
  vertical L4
  parallel L4 L6
  perpendicular L4 L7
  coincident P6 L8
  coincident P7 L8
  collinear L3 L7
  dimension "d152" distance L2 L4 = 22
  dimension "d153" distance P5 P8 = 22
extrude "Extrusion1" new body sketch "Esquisse1" profile of L4 L5 L6 L7 L8 against normal blind 22
copy_paste "CopyPaste1"
copy_paste "CopyPaste2"
as_built_joint "Réelle"
extrude "Extrusion2" add of existing geometry blind 22
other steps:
create_component "CreateComponent1"
create_component "CreateComponent2"
create_component "CreateComponent3"
create_component "CreateComponent4"
create_component "CreateComponent5"
create_component "CreateComponent6"
joint_origin "JointOrigin1" OffsetX 0 OffsetY 0 OffsetZ 0 AngleZ 0
joint_origin "JointOrigin1" OffsetX 0 OffsetY 0 OffsetZ 0 AngleZ 0
joint_origin "JointOrigin1" OffsetX 0 OffsetY 0 OffsetZ 0 AngleZ 0
joint_origin "JointOrigin2" OffsetX 0 OffsetY 0 OffsetZ 0 AngleZ 0
joint_origin "JointOrigin1" OffsetX 0 OffsetY 0 OffsetZ 0 AngleZ 0
joint_origin "JointOrigin3" OffsetX 0 OffsetY 0 OffsetZ 0 AngleZ 0
joint_origin "JointOrigin1" OffsetX 0 OffsetY 0 OffsetZ 0 AngleZ 0
joint_origin "JointOrigin1" OffsetX 0 OffsetY 0 OffsetZ 0 AngleZ 0
joint_origin "JointOrigin2" OffsetX 0 OffsetY 0 OffsetZ 0 AngleZ 0
joint_origin "JointOrigin1" OffsetX 0 OffsetY 0 OffsetZ 0 AngleZ 0
create_component "CreateComponent7"

design "Edge Beacon Left" references "EdgeBeacons_LargeBorder", "EdgeBeacons_SmallBorder", "EdgeBeacons_Base"
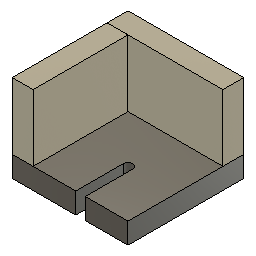
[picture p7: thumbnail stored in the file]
component_insert "Component Insert1"
ground "Ground1"
component_insert "Component Insert2"
component_insert "Component Insert3"
joint "Assemble1" OffsetX 0 OffsetY 0 OffsetZ 0 AngleZ 0 OffsetX 0 OffsetY 0 OffsetZ 0 AngleZ 0 alignAngle 0 alignOffsetX 0 alignOffsetY 0 alignOffsetZ 0
joint "Assemble2" OffsetX 0 OffsetY 0 OffsetZ 0 AngleZ 0 OffsetX 0 OffsetY 0 OffsetZ 0 AngleZ 0 alignAngle 0 alignOffsetX 0 alignOffsetY 0 alignOffsetZ 0

design "Distributeur 2 Side" references "EchantillonRouge", "EchantillonBleu", "EchantillonVert"
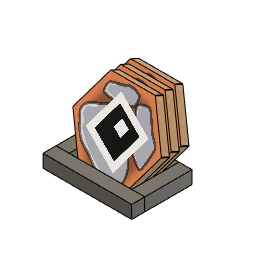
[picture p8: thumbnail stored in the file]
sketch "Esquisse1" plane through (0, 0, 0) normal (0, 1, 0) x axis (1, 0, 0)
  line L1 (-53, 11) -> (53, 11)
  line L2 (-53, -11) -> (-53, 11)
  line L3 (53, -11) -> (-53, -11)
  line L4 (53, 11) -> (53, -11)
  line L5 (-53, -11) -> (53, 11)
  line L6 (53, -11) -> (-53, 11)
  point P6 (0, 0)
  point P1 (0, 0)
  point P4 (-53, -11)
  point P5 (53, -11)
  point P3 (-53, 11)
  horizontal L1
  perpendicular L1 L2
  parallel L1 L3
  parallel L2 L4
  coincident L5 P6
  coincident L6 P6
  coincident P1 P6
  dimension "d1" distance P4 P5 = 106
  dimension "d2" distance P3 P4 = 22
  dimension "d105" OffsetX = 0
  dimension "d106" OffsetY = 0
  dimension "d107" OffsetZ = 0
  dimension "d108" AngleZ = 0
  dimension "d221" OffsetX = 0
  dimension "d222" OffsetY = 0
  dimension "d223" OffsetZ = 0
  dimension "d224" AngleZ = 0
extrude "Extrusion1" new body sketch "Esquisse1" profile of L1 L2 L3 L4 along normal blind 22
sketch "Esquisse1" plane through (0, 0, 0) normal (0, 1, 0) x axis (1, 0, 0)
  line L1 (-11, -40) -> (11, -40)
  line L2 (-11, 40) -> (-11, -40)
  line L3 (11, 40) -> (-11, 40)
  line L4 (11, -40) -> (11, 40)
  line L5 (-11, 40) -> (11, -40)
  line L6 (11, 40) -> (-11, -40)
  point P6 (0, 0)
  point P1 (0, 0)
  point P4 (-11, 40)
  point P5 (11, 40)
  point P3 (-11, -40)
  horizontal L1
  perpendicular L1 L2
  parallel L1 L3
  parallel L2 L4
  coincident L5 P6
  coincident L6 P6
  coincident P1 P6
  dimension "d5" distance P4 P5 = 22
  dimension "d6" distance P3 P4 = 80
extrude "Extrusion1" new body sketch "Esquisse1" profile of L1 L2 L3 L4 along normal blind 22
copy_paste "CopyPaste1"
joint "Assembler1" alignAngle 0 alignOffsetX 0 alignOffsetY 0 alignOffsetZ 0
joint "Assembler2" alignAngle 0 alignOffsetX 0 alignOffsetY 0 alignOffsetZ 0
sketch "Esquisse1" plane through (0, 0, 0) normal (0, 1, 0) x axis (1, 0, 0)
  line L1 (-75, -11) -> (75, -11)
  line L2 (-75, 11) -> (-75, -11)
  line L3 (75, 11) -> (-75, 11)
  line L4 (75, -11) -> (75, 11)
  line L5 (-75, 11) -> (75, -11)
  line L6 (75, 11) -> (-75, -11)
  point P6 (0, 0)
  point P1 (0, 0)
  point P4 (-75, 11)
  point P5 (75, 11)
  point P3 (-75, -11)
  horizontal L1
  perpendicular L1 L2
  parallel L1 L3
  parallel L2 L4
  coincident L5 P6
  coincident L6 P6
  coincident P1 P6
  dimension "d33" distance P4 P5 = 150
  dimension "d34" distance P3 P4 = 22
extrude "Extrusion1" new body sketch "Esquisse1" profile of L1 L2 L3 L4 along normal blind 22
joint "Assembler3" alignAngle 180 alignOffsetX 0 alignOffsetY 0 alignOffsetZ 0
sketch "Esquisse1" plane through (0, 0, 0) normal (0, 1, 0) x axis (1, 0, 0)
  line L1 (100, 50) -> (-100, 50)
  line L2 (100, 28) -> (100, 50)
  line L3 (-100, 28) -> (100, 28)
  line L4 (-100, 50) -> (-100, 28)
  point P2 (-100, 50)
  point P3 (100, 50)
  point P5 (-100, 28)
  horizontal L1
  vertical L2
  horizontal L3
  vertical L4
  dimension "d49" distance P2 P3 = 200
  dimension "d50" distance P2 P5 = 22
extrude "Extrusion1" new body sketch "Esquisse1" along normal blind 70
joint "Assembler4" alignAngle 0 alignOffsetX 0 alignOffsetY 0 alignOffsetZ 0
component_insert "Component Insert"
ground "Ground1"
ground "Ground2"
work_plane "WorkPlane1"
joint "Assemble8" OffsetX 0 OffsetY 0 OffsetZ 0 AngleZ 0 alignAngle 0 alignOffsetX 0 alignOffsetY 0 alignOffsetZ 0 OffsetX 0 OffsetY 0 OffsetZ 0 AngleZ 0
sketch "Sketch3" plane through (-53, 22, 11) normal (0, 0.4167, 0.9091) x axis (-1, 0, 0)
  point P1 (0, 0)
  point P2 (0, 0)
  coincident P1 P2
joint "Assemble12" OffsetX 0 OffsetY 0 OffsetZ 0 AngleZ 0 alignAngle 0 alignOffsetX 0 alignOffsetY 0 alignOffsetZ 0
component_insert "Insertion d'un composant7"
joint "Assembler18" alignAngle 0 alignOffsetX 0 alignOffsetY 0 alignOffsetZ 0
joint "Assembler20" alignAngle 90 alignOffsetX 0 alignOffsetY 0 alignOffsetZ 0
component_insert "Insertion d'un composant8"
joint "Assembler21" alignAngle 0 alignOffsetX 0 alignOffsetY 0 alignOffsetZ 0
joint "Assembler22" alignAngle 90 alignOffsetX 0 alignOffsetY 0 alignOffsetZ 0
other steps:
create_component "CreateComponent1" OffsetX 0 OffsetY 0 OffsetZ 0 AngleZ 0 alignAngle 90 alignOffsetX 0 alignOffsetY 0 alignOffsetZ 0
create_component "CreateComponent2"
joint_origin "JointOrigin1" OffsetX 0 OffsetY 0 OffsetZ 0 AngleZ 0
joint_origin "JointOrigin1" OffsetX 0 OffsetY 0 OffsetZ 0 AngleZ 0
joint_origin "JointOrigin2" OffsetX 0 OffsetY 0 OffsetZ 0 AngleZ 0
joint_origin "JointOrigin2" OffsetX 0 OffsetY 0 OffsetZ 0 AngleZ 0
create_component "CreateComponent3"
joint_origin "JointOrigin1" OffsetX 0 OffsetY 0 OffsetZ 0 AngleZ 0
joint_origin "JointOrigin3" OffsetX 0 OffsetY 0 OffsetZ 0 AngleZ 0
create_component "CreateComponent4"
joint_origin "JointOrigin1" OffsetX 0 OffsetY 0 OffsetZ 0 AngleZ 0
joint_origin "JointOrigin3" OffsetX 0 OffsetY 0 OffsetZ 0 AngleZ 0
joint_origin "JointOrigin5" OffsetX 0 OffsetY 0 OffsetZ 0 AngleZ 0
joint_origin "JointOrigin2" OffsetX 0 OffsetY 0 OffsetZ 0 AngleZ 0
joint_origin "JointOrigin10"
joint_origin "JointOrigin11"

design "CarreFouille" references "PCB_datation"
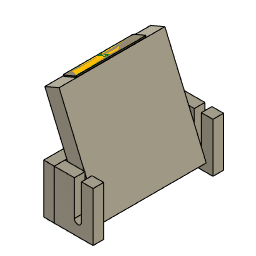
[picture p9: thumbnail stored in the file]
parameter "epMatiere" = 15 comment "Epaisseur de la planche"
parameter "diaTourillon" = 10
parameter "jeuLateral" = 5
parameter "hauteurSupport" = 70
parameter "profondeurSupport" = 70
parameter "angleInsert" = 0
parameter "epCarre" = 22
parameter "longueurTourillon" = 10 comment "longueur exterieur du tourillon"
sketch "Sketch5" plane through (0, 0, 0) normal (1, 0, 0) x axis (0, 1, 0)
  line L1 (-250, 70) -> (250, 70)
  line L2 (-250, 0) -> (-250, 70)
  line L3 (250, 0) -> (-250, 0)
  line L4 (250, 70) -> (250, 0)
  point P1 (0, 0)
  point P2 (250, 70)
  point P5 (250, 0)
  point P3 (-250, 70)
  horizontal L1
  vertical L2
  horizontal L3
  vertical L4
  midpoint P1 L3
  dimension "d81" distance P2 P5 = 70
  dimension "d82" distance P2 P3 = 500
extrude "Extrude1" new body sketch "Sketch5" along normal blind 22
ground "Ground6"
sketch "Sketch1" plane through (0, 0, 0) normal (1, 0, 0) x axis (0, 1, 0)
  line L1 (-92.5, 35) -> (92.5, 35)
  line L2 (-92.5, -35) -> (-92.5, 35)
  line L3 (92.5, -35) -> (-92.5, -35)
  line L4 (92.5, 35) -> (92.5, -35)
  line L5 (-92.5, -35) -> (92.5, 35)
  line L6 (92.5, -35) -> (-92.5, 35)
  line L7 (77.5, -35) -> (77.5, 35)
  line L8 (-77.5, -35) -> (-77.5, 35)
  point P6 (0, 0)
  point P1 (0, 0)
  point P7 (77.5, 35)
  point P8 (77.5, -35)
  point P9 (-77.5, 35)
  point P10 (-77.5, -35)
  point P2 (92.5, 35)
  point P5 (92.5, -35)
  horizontal L1
  perpendicular L1 L2
  parallel L1 L3
  parallel L2 L4
  coincident L5 P6
  coincident L6 P6
  coincident P1 P6
  coincident L1 P7
  coincident L3 P8
  perpendicular L3 L7
  coincident L1 P9
  coincident L3 P10
  perpendicular L3 L8
  dimension "d5" distance L2 L8 = 15 (= "epMatiere")
  dimension "d6" distance L4 L7 = 15 (= "epMatiere")
  dimension "d8" distance L7 L8 = 155 (= "Linear Dimension-4")
  dimension "d10" distance P2 P5 = 70 (= "hauteurSupport")
extrude "Extrude1" new body sketch "Sketch1" profile of L1 L2 L3 L4 L7 L8 against normal blind 15
extrude "Extrude1" new body sketch "Sketch1" profile of L1 L2 L3 L8 along normal blind 55 (= "profondeurSupport - epMatiere")
extrude "Extrude1" new body sketch "Sketch1" profile of L1 L3 L4 L7 along normal blind 55 (= "profondeurSupport - epMatiere")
